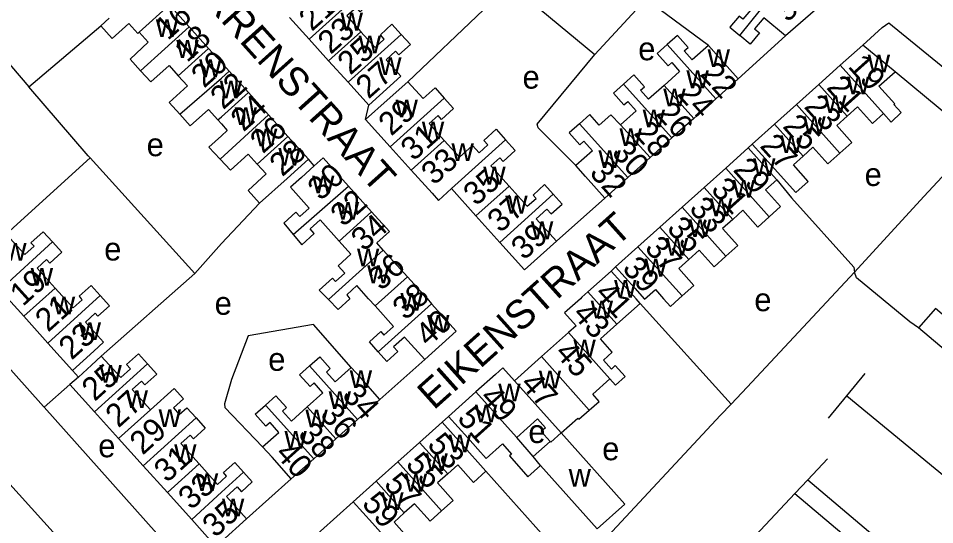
# Model space of a CAD drawing. Extents: x 158356 to 159894, y 383831 to 385260.
# Drawn here: x 159064.9 to 159223.4, y 384210.9 to 384298.5 of the extents above; entities that cross this region are included whole.
import ezdxf

# ---------------------------------------------------------------- set-up
doc = ezdxf.new("R2010")
doc.units = 0
for name, color, linetype in [('BLT_Basislijn', 7, 'Continuous'), ('BLT_Bebouwing', 7, 'Continuous'), ('BLT_Centroide', 7, 'Continuous'), ('BLT_Huisnummer', 7, 'Continuous'), ('BLT_Huisnummer_ tussenligend', 7, 'Continuous'), ('BLT_Onderverdeling_panden', 7, 'Continuous'), ('BLT_Straatnaam', 7, 'Continuous')]:
    doc.layers.add(name, color=color, linetype=linetype)

msp = doc.modelspace()

# ---------------------------------------------------------------- linework, layer by layer
at = {"layer": 'BLT_Basislijn'}
for p, q in [((159066.72, 384286.68), (159079.14, 384297.23)), ((159189.4, 384288.08), (159197.59, 384295.48)), ((159230.61, 384277.56), (159216.55, 384289.3)), ((159124.96, 384281), (159125.49, 384283.5)), ((159221.53, 384267.67), (159230.61, 384277.56)), ((159191.83, 384276.76), (159191.15, 384276.09)), ((159077.31, 384274.39), (159062.8, 384261.18)), ((159077.31, 384274.39), (159095.41, 384254.35)), ((159116.06, 384272.99), (159115.09, 384274.14)), ((159166.34, 384267.43), (159157.96, 384259.98)), ((159209.5, 384254.57), (159221.53, 384267.67)), ((159167.45, 384254.79), (159168.2, 384255.53)), ((159095.41, 384254.35), (159079.24, 384240.07)), ((159172.45, 384249.2), (159188.16, 384231.76)), ((159135.18, 384239.48), (159127.44, 384232.56)), ((159075.27, 384236.44), (159074.26, 384237.59)), ((159205, 384229.32), (159211.36, 384237.03)), ((159073.82, 384235.13), (159069.33, 384231.23)), ((159208.18, 384233.17), (159244.02, 384203.65)), ((159188.16, 384231.76), (159186.36, 384229.83)), ((159139.3, 384229.62), (159138.19, 384228.62)), ((159186.36, 384229.83), (159161.21, 384202.88)), ((159059.38, 384222.36), (159076.26, 384203.68)), ((159201.44, 384218.65), (159204.87, 384222.29)), ((159145.77, 384220.13), (159161.21, 384202.88)), ((159104.36, 384211.88), (159112.1, 384218.83)), ((159199.22, 384216.28), (159201.44, 384218.65)), ((159201.44, 384218.65), (159233.85, 384191.31)), ((159199.22, 384216.28), (159173.63, 384189.04)), ((159199.22, 384216.28), (159231.79, 384188.8)), ((159122.8, 384214.86), (159111.22, 384204.49))]:
    msp.add_line(p, q, dxfattribs=at)
for points in [[(159046.11, 384310.29), (159055.27, 384300), (159066.72, 384286.68)], [(159150.18, 384304.55), (159145.33, 384300), (159132.25, 384287.56)], [(159153.84, 384301.33), (159155.28, 384300), (159164.63, 384292.26)], [(159184.24, 384293.85), (159175.91, 384300), (159173.88, 384301.5), (159172.96, 384301.5), (159171.73, 384300), (159164.63, 384292.26)], [(159210.97, 384293.91), (159214.28, 384296.93), (159215.48, 384297.74), (159262.59, 384259.31)], [(159161.31, 384273.04), (159154.8, 384279.57), (159154.61, 384280.2), (159164.63, 384292.26)], [(159077.31, 384274.39), (159076.98, 384274.75), (159066.72, 384286.68)], [(159196.08, 384270.6), (159198.65, 384267.44), (159209.38, 384255.48), (159209.5, 384254.57)], [(159106.63, 384266.52), (159100, 384259.57), (159095.41, 384254.35)], [(159209.5, 384254.57), (159190.93, 384234.7), (159188.16, 384231.76)], [(159220.59, 384244.95), (159219.09, 384246.02), (159209.86, 384253.6), (159209.5, 384254.57)], [(159069.33, 384231.23), (159069.23, 384231.34), (159051.7, 384250.96)], [(159227.82, 384244.65), (159223.54, 384248.33), (159220.59, 384244.95)], [(159122.48, 384238.1), (159115.97, 384245.55), (159104.67, 384243.59), (159101.77, 384236.04), (159100.55, 384231.82), (159100.59, 384231.18), (159107.14, 384224.34)], [(159247.96, 384221.99), (159246.23, 384223.49), (159227.24, 384239.36), (159220.59, 384244.95)], [(159069.33, 384231.23), (159092.65, 384205.09), (159094.57, 384203.25), (159095.11, 384203.47), (159099.07, 384207.11)]]:
    msp.add_lwpolyline(points, dxfattribs=at)
at = {"layer": 'BLT_Bebouwing'}
for p, q in [((159080.61, 384298.56), (159079.14, 384297.23)), ((159115.22, 384294.9), (159111.8, 384298.7)), ((159097.8, 384293.33), (159094.44, 384297.06)), ((159118.56, 384291.19), (159115.22, 384294.9)), ((159210.97, 384293.91), (159207.06, 384290.41)), ((159216.55, 384289.3), (159210.97, 384293.91)), ((159121.92, 384287.46), (159118.56, 384291.19)), ((159207.06, 384290.41), (159203.34, 384287.08)), ((159104.68, 384285.69), (159101.34, 384289.41)), ((159189.4, 384288.08), (159185.53, 384284.62)), ((159125.49, 384283.5), (159121.92, 384287.46)), ((159203.34, 384287.08), (159199.46, 384283.6)), ((159108.14, 384281.85), (159104.68, 384285.69)), ((159185.53, 384284.62), (159181.71, 384281.2)), ((159199.46, 384283.6), (159195.69, 384280.22)), ((159111.53, 384278.09), (159108.14, 384281.85)), ((159124.96, 384281), (159129.22, 384276.28)), ((159181.71, 384281.2), (159177.94, 384277.82)), ((159195.69, 384280.22), (159191.83, 384276.76)), ((159115.09, 384274.14), (159111.53, 384278.09)), ((159177.94, 384277.82), (159174.15, 384274.42)), ((159129.22, 384276.28), (159132.85, 384272.25)), ((159191.15, 384276.09), (159187.24, 384272.59)), ((159174.15, 384274.42), (159170.3, 384270.97)), ((159187.24, 384272.59), (159183.51, 384269.25)), ((159170.3, 384270.97), (159166.34, 384267.43)), ((159125.98, 384265.05), (159121.97, 384269.5)), ((159139.79, 384269.05), (159144.03, 384264.34)), ((159183.51, 384269.25), (159179.7, 384265.83)), ((159179.7, 384265.83), (159175.86, 384262.4)), ((159144.03, 384264.34), (159148.17, 384259.74)), ((159175.86, 384262.4), (159172.07, 384259)), ((159132.2, 384253.76), (159128.02, 384258.4)), ((159172.07, 384259), (159168.2, 384255.53)), ((159167.45, 384254.79), (159163.41, 384251.18)), ((159135.58, 384250.01), (159132.2, 384253.76)), ((159074.35, 384248.4), (159071.23, 384251.85)), ((159125.48, 384250), (159123.45, 384252.26)), ((159063.07, 384250.01), (159065.82, 384246.96)), ((159080.66, 384248.78), (159079.07, 384250.54)), ((159125.48, 384250), (159126.62, 384248.74)), ((159135.58, 384250.01), (159136.36, 384249.14)), ((159162.38, 384250.25), (159163.41, 384251.18)), ((159172.45, 384249.2), (159171.74, 384250)), ((159176.5, 384250), (159177.68, 384248.68)), ((159168.41, 384245.59), (159172.45, 384249.2)), ((159065.82, 384246.96), (159069.98, 384242.33)), ((159160.04, 384244.14), (159155.38, 384239.98)), ((159069.98, 384242.33), (159074.26, 384237.59)), ((159155.38, 384239.98), (159150.71, 384235.81)), ((159075.27, 384236.44), (159073.82, 384235.13)), ((159073.82, 384235.13), (159078.06, 384230.43)), ((159127.44, 384232.56), (159123.58, 384229.1)), ((159144.05, 384233.87), (159139.3, 384229.62)), ((159078.06, 384230.43), (159082.24, 384225.79)), ((159123.58, 384229.1), (159119.81, 384225.72)), ((159138.19, 384228.62), (159134.28, 384225.12)), ((159082.24, 384225.79), (159086.46, 384221.1)), ((159119.81, 384225.72), (159115.98, 384222.3)), ((159134.28, 384225.12), (159130.53, 384221.77)), ((159153.92, 384222.66), (159151.09, 384225.99)), ((159156.88, 384225.29), (159153.92, 384222.66)), ((159115.98, 384222.3), (159112.1, 384218.83)), ((159130.53, 384221.77), (159126.76, 384218.4)), ((159086.46, 384221.1), (159090.67, 384216.43)), ((159126.76, 384218.4), (159122.8, 384214.86)), ((159090.67, 384216.43), (159094.87, 384211.77)), ((159094.87, 384211.77), (159099.07, 384207.11))]:
    msp.add_line(p, q, dxfattribs=at)
for points in [[(159124.4, 384303.27), (159126.02, 384301.48), (159124.38, 384300), (159124.02, 384299.67), (159123.73, 384300), (159123.35, 384300.42), (159122.89, 384300), (159121.71, 384298.94), (159124.15, 384296.22)], [(159187.98, 384303.03), (159191.57, 384300), (159190.21, 384298.38), (159189.57, 384298.91), (159187.97, 384296.99), (159189.71, 384295.54)], [(159094.44, 384297.06), (159091.79, 384300), (159091.01, 384300.87)], [(159203.14, 384300.3), (159202.79, 384300), (159197.59, 384295.48)], [(159079.14, 384297.23), (159081.13, 384295.02), (159084.01, 384297.61), (159085.53, 384295.93), (159085.78, 384296.16)], [(159124.15, 384296.22), (159126.6, 384293.51), (159128.18, 384294.94), (159127.51, 384295.69), (159129.52, 384297.5), (159131.11, 384295.74)], [(159197.59, 384295.48), (159193.82, 384298.63), (159192.22, 384296.72), (159193.07, 384296.02), (159191.45, 384294.08), (159189.71, 384295.54)], [(159085.78, 384296.16), (159087.37, 384294.4), (159084.24, 384291.49), (159086, 384289.46)], [(159131.11, 384295.74), (159132.7, 384293.98), (159130.72, 384292.19), (159130.14, 384292.83), (159128.51, 384291.36), (159131.05, 384288.53), (159129.2, 384286.85), (159125.49, 384283.5)], [(159184.24, 384293.85), (159181.45, 384291.35), (159180.06, 384292.9), (159180.73, 384293.5), (159178.88, 384295.57), (159177.12, 384294)], [(159101.34, 384289.41), (159100, 384290.89), (159097.8, 384293.33)], [(159177.12, 384294), (159175.37, 384292.43), (159177.27, 384290.3), (159177.9, 384290.86), (159179.27, 384289.33), (159176.58, 384286.92)], [(159189.4, 384288.08), (159186.06, 384291.81), (159184.24, 384293.85)], [(159086, 384289.46), (159087.8, 384287.52), (159090.95, 384290.39), (159092.56, 384288.6)], [(159092.56, 384288.6), (159094.17, 384286.82), (159090.98, 384283.94), (159092.8, 384281.92)], [(159176.58, 384286.92), (159173.89, 384284.52), (159172.5, 384286.07), (159173.17, 384286.67), (159171.33, 384288.73), (159169.57, 384287.16)], [(159214.55, 384282.05), (159215.87, 384280.58), (159217.61, 384282.21), (159216.33, 384283.64), (159216.47, 384283.76), (159213.75, 384286.79), (159216.55, 384289.3)], [(159132.25, 384287.56), (159128.68, 384284.35), (159124.96, 384281)], [(159132.25, 384287.56), (159134.89, 384284.63), (159136.96, 384286.49), (159138.56, 384284.71)], [(159169.57, 384287.16), (159167.82, 384285.59), (159169.65, 384283.54), (159170.3, 384284.12), (159171.74, 384282.52), (159169.05, 384280.11)], [(159138.56, 384284.71), (159140.17, 384282.92), (159138.09, 384281.04), (159137.49, 384281.71), (159135.93, 384280.31), (159138.56, 384277.4)], [(159208.25, 384281.61), (159210.05, 384283.22), (159212.64, 384280.33), (159212.74, 384280.43), (159214.55, 384282.05)], [(159092.8, 384281.92), (159094.62, 384279.9), (159097.78, 384282.74), (159099.4, 384280.94)], [(159169.05, 384280.11), (159167.36, 384281.81), (159165.37, 384280.03), (159163.72, 384281.87), (159161.95, 384280.29)], [(159206.99, 384275.2), (159209.06, 384277.06), (159206.44, 384279.99), (159208.25, 384281.61)], [(159099.4, 384280.94), (159100, 384280.27), (159101.03, 384279.13), (159100, 384278.2), (159097.86, 384276.26), (159099.77, 384274.18)], [(159161.95, 384280.29), (159160.18, 384278.7), (159162.01, 384276.66), (159162.69, 384277.28), (159164.18, 384275.62), (159161.31, 384273.04)], [(159138.56, 384277.4), (159141.18, 384274.48), (159143.45, 384276.52), (159144.57, 384275.27), (159146.09, 384276.65), (159145.43, 384277.39), (159147.51, 384279.34), (159149.17, 384277.49)], [(159149.17, 384277.49), (159150.83, 384275.65), (159148.73, 384273.76), (159148.15, 384274.4), (159146.61, 384273.01), (159149.77, 384269.51)], [(159196.08, 384270.6), (159194.49, 384272.37), (159191.15, 384276.09)], [(159191.83, 384276.76), (159195.17, 384273.04), (159199.36, 384268.36), (159201.52, 384270.3), (159198.95, 384273.16), (159200.65, 384274.68)], [(159200.65, 384274.68), (159202.34, 384276.21), (159204.91, 384273.34), (159206.99, 384275.2)], [(159099.77, 384274.18), (159101.57, 384272.27), (159104.67, 384275.04), (159106.22, 384273.31)], [(159115.09, 384274.14), (159111.38, 384270.79), (159106.63, 384266.52)], [(159121.97, 384269.5), (159117.59, 384274.36), (159116.06, 384272.99)], [(159106.22, 384273.31), (159107.78, 384271.59), (159104.62, 384268.74), (159106.63, 384266.52)], [(159116.06, 384272.99), (159113.88, 384271.01), (159111.96, 384269.29), (159115.2, 384265.7), (159113.56, 384264.22), (159112.88, 384264.97), (159110.79, 384263.08), (159112.42, 384261.14)], [(159132.85, 384272.25), (159136.44, 384268.26), (159137.58, 384266.99), (159139.79, 384269.05)], [(159166.34, 384267.43), (159163.01, 384271.15), (159161.31, 384273.04)], [(159196.08, 384270.6), (159194.13, 384268.86), (159196.74, 384265.95), (159194.77, 384264.18)], [(159149.77, 384269.51), (159152.92, 384266.01), (159154.43, 384267.37), (159153.91, 384267.95), (159155.91, 384269.76), (159157.42, 384268.07)], [(159157.96, 384259.98), (159154.47, 384263.85), (159156.32, 384265.51), (159157.06, 384264.7), (159158.94, 384266.39), (159157.42, 384268.07)], [(159128.02, 384258.4), (159126.88, 384259.66), (159129.06, 384261.63), (159125.98, 384265.05)], [(159194.77, 384264.18), (159192.8, 384262.41), (159190.21, 384265.3), (159188.46, 384263.73)], [(159112.42, 384261.14), (159113.91, 384259.35), (159116.06, 384261.29), (159115.34, 384262.09), (159117.07, 384263.64), (159120.36, 384259.99)], [(159188.46, 384263.73), (159186.71, 384262.16), (159189.36, 384259.2), (159187.29, 384257.35)], [(159070.8, 384259.82), (159069.19, 384261.6), (159067.07, 384259.69), (159067.6, 384259.1), (159065.99, 384257.65), (159062.8, 384261.18)], [(159071.23, 384251.85), (159068.12, 384255.3), (159069.78, 384256.8), (159070.35, 384256.17), (159072.41, 384258.04), (159070.8, 384259.82)], [(159120.36, 384259.99), (159122.42, 384257.7), (159120.21, 384255.7), (159121.34, 384254.44), (159119.72, 384252.98), (159119.22, 384253.54), (159116.93, 384251.48), (159118.53, 384249.84)], [(159148.17, 384259.74), (159152.44, 384255), (159157.96, 384259.98)], [(159187.29, 384257.35), (159185.23, 384255.5), (159182.65, 384258.38), (159180.88, 384256.79)], [(159180.88, 384256.79), (159179.12, 384255.21), (159181.72, 384252.3), (159179.7, 384250.49)], [(159167.45, 384254.79), (159170.78, 384251.07), (159171.74, 384250)], [(159168.2, 384255.53), (159171.54, 384251.8), (159173.21, 384249.93)], [(159079.07, 384250.54), (159077.47, 384252.31), (159075.4, 384250.43), (159075.78, 384250)], [(159123.45, 384252.26), (159121.71, 384250.7), (159122.25, 384249.97)], [(159173.21, 384249.93), (159175.07, 384251.59), (159176.5, 384250)], [(159074.35, 384248.4), (159075.93, 384249.83), (159075.78, 384250)], [(159122.25, 384249.97), (159120.19, 384248.11), (159118.53, 384249.84)], [(159162.38, 384250.25), (159162.1, 384250), (159159.37, 384247.57), (159161.37, 384245.33), (159160.04, 384244.14)], [(159179.7, 384250.49), (159179.14, 384249.99), (159177.68, 384248.68)], [(159074.26, 384237.59), (159077.97, 384240.93), (159079.62, 384242.46), (159076.49, 384245.95), (159078.18, 384247.47), (159078.64, 384246.96), (159080.66, 384248.78)], [(159127.13, 384240.83), (159125.61, 384242.51), (159127.59, 384244.3), (159128.13, 384243.71), (159129.8, 384245.21), (159126.62, 384248.74)], [(159136.36, 384249.14), (159140.64, 384244.4), (159135.18, 384239.48)], [(159167.2, 384236.13), (159168.17, 384235.04), (159169.83, 384236.53), (159168.14, 384238.42), (159167.48, 384237.83), (159166.08, 384239.39), (159167.61, 384240.76), (159165.57, 384243.04), (159168.41, 384245.59)], [(159135.18, 384239.48), (159131.68, 384243.36), (159129.8, 384241.66), (159130.53, 384240.84), (159128.65, 384239.14), (159127.13, 384240.83)], [(159079.24, 384240.07), (159082.61, 384236.37), (159084.27, 384237.87), (159083.6, 384238.62), (159085.65, 384240.47), (159087.25, 384238.71)], [(159079.24, 384240.07), (159077.54, 384238.48), (159075.27, 384236.44)], [(159115.27, 384238.38), (159117.01, 384239.94), (159118.84, 384237.91), (159118.17, 384237.31), (159119.69, 384235.61), (159122.48, 384238.1)], [(159087.25, 384238.71), (159088.84, 384236.94), (159086.78, 384235.09), (159086.2, 384235.74), (159084.58, 384234.28), (159087.75, 384230.76)], [(159114.84, 384231.26), (159117.57, 384233.7), (159116.04, 384235.42), (159115.35, 384234.8), (159113.53, 384236.83), (159115.27, 384238.38)], [(159127.44, 384232.56), (159124.11, 384236.28), (159122.48, 384238.1)], [(159150.71, 384235.81), (159148.71, 384238.04), (159147.4, 384236.87), (159144.05, 384233.87)], [(159163.65, 384230.71), (159165.38, 384232.23), (159164.25, 384233.49), (159167.2, 384236.13)], [(159087.75, 384230.76), (159091.84, 384234.44), (159093.45, 384232.65), (159091.7, 384231.09), (159092.71, 384229.97), (159094.02, 384231.14), (159095.62, 384229.36)], [(159107.65, 384231.6), (159109.45, 384233.21), (159111.27, 384231.18), (159110.57, 384230.55), (159112.12, 384228.82), (159114.84, 384231.26)], [(159107.14, 384224.34), (159109.96, 384226.87), (159108.43, 384228.58), (159107.7, 384227.93), (159105.86, 384229.99), (159107.65, 384231.6)], [(159095.62, 384229.36), (159097.23, 384227.57), (159095.21, 384225.75), (159094.63, 384226.39), (159093.01, 384224.93), (159096.18, 384221.4)], [(159139.3, 384229.62), (159142.63, 384225.9), (159144.38, 384223.94), (159145.79, 384222.36), (159148.62, 384224.9), (159150.21, 384223.08), (159149.87, 384222.78), (159153.01, 384219.18), (159155.23, 384221.12)], [(159158.78, 384226.78), (159161.65, 384229.35), (159161.84, 384229.14), (159163.65, 384230.71)], [(159145.77, 384220.13), (159141.52, 384224.89), (159138.19, 384228.62)], [(159151.09, 384225.99), (159154.67, 384229.2), (159156.05, 384227.66), (159155.32, 384227.01), (159156.88, 384225.29)], [(159155.23, 384221.12), (159165.02, 384210.17), (159169.8, 384214.45), (159158.78, 384226.78)], [(159112.1, 384218.83), (159108.77, 384222.55), (159107.14, 384224.34)], [(159096.18, 384221.4), (159099.36, 384217.87), (159100, 384218.45), (159100.91, 384219.27), (159100.35, 384219.89), (159102.32, 384221.67), (159103.84, 384219.98)], [(159104.36, 384211.88), (159100.88, 384215.74), (159102.73, 384217.41), (159103.47, 384216.59), (159105.36, 384218.29), (159103.84, 384219.98)], [(159145.77, 384220.13), (159143.62, 384218.21), (159140.91, 384221.25), (159139.15, 384219.68)], [(159139.15, 384219.68), (159137.39, 384218.11), (159140.1, 384215.08), (159138.1, 384213.29)], [(159122.8, 384214.86), (159126.14, 384211.13), (159130.32, 384206.45)], [(159138.1, 384213.29), (159136.11, 384211.51), (159133.43, 384214.5), (159131.65, 384212.92)], [(159099.07, 384207.11), (159100, 384207.95), (159104.36, 384211.88)], [(159131.65, 384212.92), (159129.88, 384211.33), (159132.51, 384208.4), (159130.32, 384206.45)]]:
    msp.add_lwpolyline(points, dxfattribs=at)
at = {"layer": 'BLT_Onderverdeling_panden'}
for p, q in [((159124.4, 384303.27), (159115.22, 384294.9)), ((159085.78, 384296.16), (159091.01, 384300.87)), ((159086, 384289.46), (159094.44, 384297.06)), ((159124.15, 384296.22), (159118.56, 384291.19)), ((159131.11, 384295.74), (159121.92, 384287.46)), ((159092.56, 384288.6), (159097.8, 384293.33)), ((159177.12, 384294), (159185.53, 384284.62)), ((159214.55, 384282.05), (159207.06, 384290.41)), ((159169.57, 384287.16), (159177.94, 384277.82)), ((159176.58, 384286.92), (159181.71, 384281.2)), ((159208.25, 384281.61), (159203.34, 384287.08)), ((159138.56, 384284.71), (159129.22, 384276.28)), ((159206.99, 384275.2), (159199.46, 384283.6)), ((159099.77, 384274.18), (159108.14, 384281.85)), ((159161.95, 384280.29), (159170.3, 384270.97)), ((159169.05, 384280.11), (159174.15, 384274.42)), ((159200.65, 384274.68), (159195.69, 384280.22)), ((159106.22, 384273.31), (159111.53, 384278.09)), ((159138.56, 384277.4), (159132.85, 384272.25)), ((159149.17, 384277.49), (159139.79, 384269.05)), ((159194.77, 384264.18), (159187.24, 384272.59)), ((159112.42, 384261.14), (159121.97, 384269.5)), ((159149.77, 384269.51), (159144.03, 384264.34)), ((159188.46, 384263.73), (159183.51, 384269.25)), ((159157.42, 384268.07), (159148.17, 384259.74)), ((159187.29, 384257.35), (159179.7, 384265.83)), ((159120.36, 384259.99), (159125.98, 384265.05)), ((159180.88, 384256.79), (159175.86, 384262.4)), ((159070.8, 384259.82), (159061.66, 384251.56)), ((159118.53, 384249.84), (159128.02, 384258.4)), ((159179.7, 384250.49), (159172.07, 384259)), ((159126.62, 384248.74), (159132.2, 384253.76)), ((159071.23, 384251.85), (159065.82, 384246.96)), ((159079.07, 384250.54), (159069.98, 384242.33)), ((159163.41, 384251.18), (159168.41, 384245.59)), ((159127.13, 384240.83), (159136.36, 384249.14)), ((159160.04, 384244.14), (159167.2, 384236.13)), ((159155.38, 384239.98), (159163.65, 384230.71)), ((159087.25, 384238.71), (159078.06, 384230.43)), ((159115.27, 384238.38), (159123.58, 384229.1)), ((159150.71, 384235.81), (159158.78, 384226.78)), ((159144.05, 384233.87), (159150.54, 384226.61)), ((159107.65, 384231.6), (159115.98, 384222.3)), ((159114.84, 384231.26), (159119.81, 384225.72)), ((159087.75, 384230.76), (159082.24, 384225.79)), ((159095.62, 384229.36), (159086.46, 384221.1)), ((159150.54, 384226.61), (159151.09, 384225.99)), ((159139.15, 384219.68), (159134.28, 384225.12)), ((159096.18, 384221.4), (159090.67, 384216.43)), ((159138.1, 384213.29), (159130.53, 384221.77)), ((159155.23, 384221.12), (159153.92, 384222.66)), ((159131.65, 384212.92), (159126.76, 384218.4))]:
    msp.add_line(p, q, dxfattribs=at)
for points in [[(159189.71, 384295.54), (159193.27, 384300), (159197.46, 384305.03)], [(159092.8, 384281.92), (159100, 384288.2), (159101.34, 384289.41)], [(159099.4, 384280.94), (159100, 384281.47), (159104.68, 384285.69)], [(159156.88, 384225.29), (159157.01, 384225.15), (159158.78, 384226.78)], [(159094.87, 384211.77), (159100, 384216.53), (159103.84, 384219.98)]]:
    msp.add_lwpolyline(points, dxfattribs=at)

# ---------------------------------------------------------------- texts
at = {"layer": 'BLT_Centroide'}
for s, p in [('w', (159120.62, 384296.42)), ('w', (159088.67, 384295.31)), ('w', (159092.22, 384291.69)), ('w', (159123.75, 384292.47)), ('e', (159172.11, 384291.27)), ('w', (159184.11, 384290.09)), ('w', (159096.16, 384288.34)), ('w', (159127.31, 384288.73)), ('w', (159211.81, 384289.17)), ('e', (159152.1, 384286.36)), ('w', (159180.45, 384286.44)), ('w', (159208.23, 384285.38)), ('w', (159099.73, 384284.66)), ('w', (159176.45, 384283.28)), ('w', (159204.27, 384282.16)), ('w', (159130.13, 384281.38)), ('w', (159102.3, 384280.06)), ('w', (159172.88, 384279.66)), ('w', (159134.69, 384277.56)), ('w', (159200.66, 384278.47)), ('w', (159105.83, 384276.38)), ('w', (159168.88, 384276.41)), ('e', (159087.08, 384274.67)), ('w', (159139.81, 384273.81)), ('w', (159196.67, 384275.23)), ('w', (159109.86, 384273.02)), ('w', (159165.23, 384272.64)), ('w', (159191.98, 384271.22)), ('w', (159145.31, 384269.77)), ('e', (159211.27, 384269.51)), ('w', (159115.7, 384268.25)), ('w', (159188.44, 384267.5)), ('w', (159149.11, 384264.75)), ('w', (159184.53, 384264.28)), ('w', (159119.98, 384263.69)), ('w', (159153.55, 384260.3)), ('w', (159180.88, 384260.66)), ('w', (159062.45, 384256.59)), ('e', (159079.74, 384256.61)), ('w', (159176.89, 384257.44)), ('w', (159123.46, 384255.62)), ('w', (159173.21, 384253.84)), ('w', (159067.03, 384252.23)), ('w', (159125.23, 384252.69)), ('w', (159167.94, 384250.19)), ('w', (159070.86, 384247.31)), ('e', (159098.84, 384247.22)), ('w', (159130.98, 384247.91)), ('e', (159192.19, 384247.84)), ('w', (159163.89, 384246.58)), ('w', (159135.59, 384244.12)), ('w', (159075.33, 384242.86)), ('w', (159160.9, 384239.84)), ('e', (159108.11, 384237.52)), ('w', (159078.91, 384235.44)), ('w', (159122.21, 384234.53)), ('w', (159154.91, 384234.5)), ('w', (159083.45, 384231.08)), ('w', (159147.91, 384232.22)), ('w', (159118.56, 384230.92)), ('w', (159143.86, 384228.59)), ('w', (159089.15, 384227.78)), ('w', (159114.54, 384227.75)), ('e', (159153.11, 384225.02)), ('w', (159110.92, 384224.05)), ('w', (159139.33, 384223.41)), ('e', (159078.71, 384222.55)), ('w', (159091.84, 384221.73)), ('e', (159165.88, 384222.04)), ('w', (159135.31, 384220.19)), ('w', (159095.6, 384216.72)), ('w', (159160.07, 384217.48)), ('w', (159131.72, 384216.62)), ('w', (159100.11, 384212.34)), ('w', (159127.66, 384213.42))]:
    msp.add_text(s, height=4, dxfattribs=at).set_placement(p)
at = {"layer": 'BLT_Huisnummer'}
for s, rotation, p in [('34', 50.2209, (159198.13, 384297.68)), ('21', 41.7437, (159115.65, 384296.16)), ('18', 41.9005, (159094.07, 384290.77)), ('27', 41.7437, (159125.47, 384284.46)), ('19', 311.8563, (159208.24, 384290.14)), ('22', 311.8632, (159182.64, 384288.79)), ('22', 41.9005, (159100.32, 384282.6)), ('23', 311.8563, (159200.65, 384283.16)), ('29', 41.7437, (159129.39, 384278.03)), ('26', 311.8632, (159175, 384281.93)), ('27', 311.8563, (159193, 384276.36)), ('28', 41.9005, (159110.55, 384271)), ('33', 41.7437, (159136.79, 384269.5)), ('32', 311.8632, (159163.53, 384271.67)), ('29', 311.8563, (159188.36, 384272.23)), ('30', 41.9005, (159117.16, 384266.82)), ('33', 311.8563, (159180.76, 384265.47)), ('34', 41.9005, (159124.67, 384258.06)), ('39', 41.7437, (159152.35, 384256.53)), ('39', 311.8563, (159169.2, 384255.12)), ('41', 311.8563, (159164.44, 384250.77)), ('40', 41.9005, (159135.8, 384241.55)), ('23', 42.102, (159074.11, 384239.26)), ('45', 311.8563, (159157.52, 384240.5)), ('25', 42.102, (159078.1, 384232.11)), ('34', 311.8344, (159120.72, 384233.17)), ('51', 311.8563, (159140.64, 384229.16)), ('29', 42.102, (159086.39, 384222.81)), ('53', 311.8563, (159135.45, 384224.6)), ('40', 311.8279, (159109.15, 384223.04)), ('59', 311.8563, (159124.15, 384214.4)), ('35', 42.102, (159098.96, 384208.5))]:
    msp.add_text(s, height=4, rotation=rotation, dxfattribs=at).set_placement(p)
at = {"layer": 'BLT_Huisnummer_ tussenligend'}
for s, rotation, p in [('16', 41.9005, (159090.75, 384294.6)), ('23', 41.7437, (159118.9, 384292.16)), ('25', 41.7437, (159122.31, 384288.59)), ('20', 41.9005, (159097.02, 384286.34)), ('21', 311.8563, (159204.52, 384286.48)), ('24', 311.8632, (159178.69, 384285.34)), ('24', 41.9005, (159103.84, 384278.77)), ('26', 41.9005, (159107.19, 384274.99)), ('25', 311.8563, (159196.95, 384279.75)), ('28', 311.8632, (159171.18, 384278.57)), ('31', 41.7437, (159133.25, 384273.69)), ('30', 311.8632, (159167.36, 384275.17)), ('35', 41.7437, (159144.07, 384265.91)), ('31', 311.8563, (159184.53, 384268.78)), ('32', 41.9005, (159121.11, 384262.3)), ('37', 41.7437, (159148.24, 384261.26)), ('35', 311.8563, (159176.9, 384262.05)), ('37', 311.8563, (159173.06, 384258.65)), ('36', 41.9005, (159127.65, 384251.25)), ('19', 42.102, (159065.67, 384248.55)), ('38', 41.9005, (159131.84, 384246.13)), ('21', 42.102, (159070.04, 384244.09)), ('43', 311.8563, (159160.58, 384247.22)), ('47', 311.8563, (159151.54, 384235.12)), ('27', 42.102, (159082.2, 384227.52)), ('49', 311.8563, (159144.54, 384232.76)), ('36', 311.8344, (159116.91, 384229.77)), ('38', 311.8344, (159113.1, 384226.41)), ('31', 42.102, (159090.6, 384218.01)), ('55', 311.8563, (159131.73, 384221.22)), ('57', 311.8563, (159127.95, 384217.75)), ('33', 42.102, (159094.79, 384213.3))]:
    msp.add_text(s, height=4, rotation=rotation, dxfattribs=at).set_placement(p)
at = {"layer": 'BLT_Straatnaam'}
for s, height, rotation, p in [('SPARRENSTRAAT', 5, 311.9587, (159087.58, 384311.68)), ('EIKENSTRAAT', 4.9999, 41.8438, (159136.75, 384230.61))]:
    msp.add_text(s, height=height, rotation=rotation, dxfattribs=at).set_placement(p)

doc.saveas('drawing.dxf')
